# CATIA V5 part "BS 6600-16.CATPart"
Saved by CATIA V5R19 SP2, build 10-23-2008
Part number: BS 6600-16
Bounding box of the stored display mesh (mm): x -59.975 to 59.975, y -59.975 to 59.975, z 0 to 107
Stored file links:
  C:\Users\Bora\Desktop\3D Katı model\BS serisi\BS 6600\BS 6600-16.CATPart
  C:\Program Files\Dassault Systemes\B19\intel_a\reffiles\standard\MetricThickPitch.txt
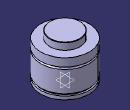
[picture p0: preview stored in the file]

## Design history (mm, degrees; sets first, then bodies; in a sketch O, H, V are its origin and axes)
Body1 (main body)
  Sketch1 on yz-plane, origin (0, 0, 0), H (0, 1, 0), V (0, 0, 1)
    point P1 (60, 70)
    point P2 (60, 65)
    point P3 (60, 70)
    point P7 (37.5, 106)
    point P9 (37.5, 106)
    point P14 (60, 65)
    arc A1 centre (60, 67.5) radius 2.5 from (60, 70) to (60, 65) ccw
    line L1 (60, 70) -> (60, 90)
    line L2 (60, 0) -> (60, 8)
    arc A2 centre (36.5, 106) radius 1 from (37.5, 106) to (36.5, 107) ccw
    line L3 (37.5, 106) -> (37.5, 90)
    line L4 (56, 13) -> (56, 8)
    line L5 (60, 13) -> (60, 65)
    line L6 (36.5, 107) -> (0, 107)
    point P15 (0, 107)
    line L7 (37.5, 90) -> (60, 90)
    line L8 (56, 13) -> (60, 13)
    line L9 (56, 8) -> (60, 8)
    line L10 (60, 0) -> (0, 0)
    coincidence: P15 V, P1 P3, P2 P14, P7 P9
    tangency: L6 A2
    horizontal: L7 H, L8 H, L9 H, L10 H
  Shaft1: profile Sketch1, axis Sketch1.V, angle 360
  Sketch2 on face of Shaft1 from Sketch1.L10, origin (0, 0, 0), H (1, 0, 0), V (0, -1, 0)
    point P1 (40, 0)
    distance P1 V = 40
  Hole1: placed by Sketch2, at (40, 0, 0) direction (0, 0, 1), diameter 8.376, depth 8, threaded "M10", thread diameter 10, thread depth 8, pitch 1.5
  CircPattern1: of Hole1, instances 4, angular step 90, axis from xy-plane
